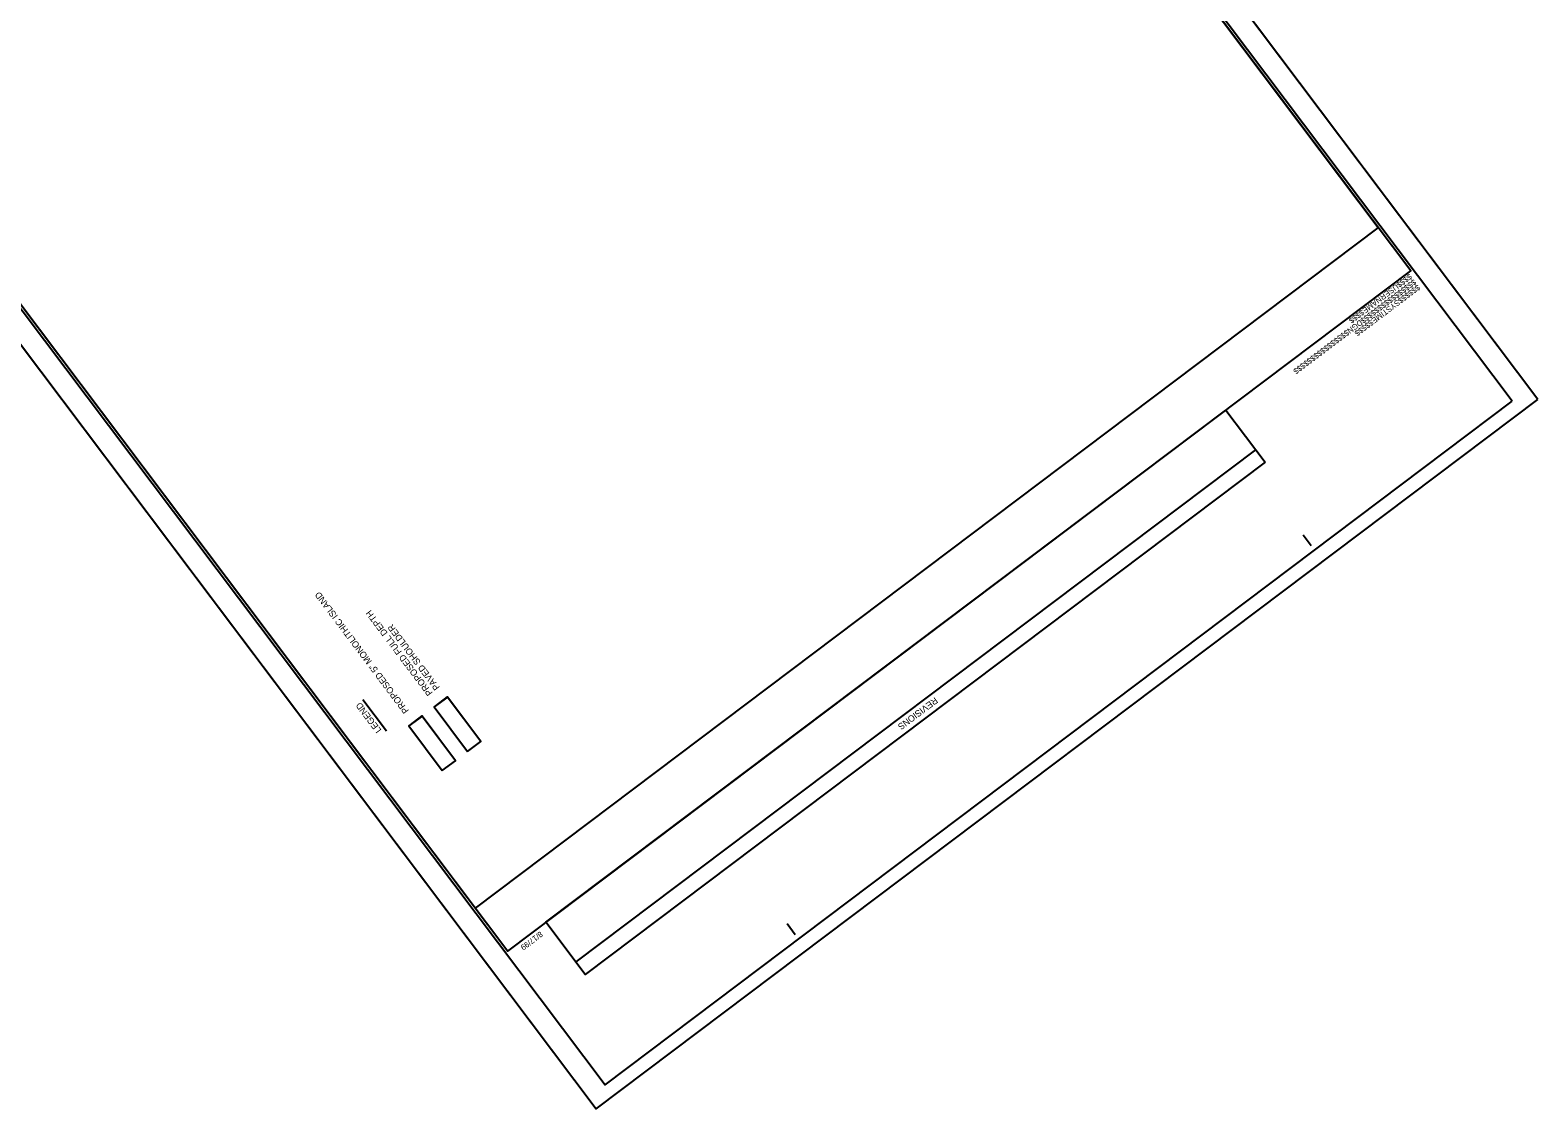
# Model space of a CAD drawing. Extents: x 1262749 to 1264921, y 774795 to 776798.
# Drawn here: x 1263520 to 1264921, y 774795 to 775796 of the extents above; entities that cross this region are included whole.
import ezdxf

# ---------------------------------------------------------------- set-up
doc = ezdxf.new("R2010")
doc.units = 0
for name, color, linetype in [('Old_Level_1', 7, 'Continuous'), ('Prop Shade Light', 7, 'Continuous'), ('Prop Shade Medium', 7, 'Continuous'), ('Sheet Block Revision CELL', 7, 'Continuous'), ('Sheet Clip Boundary CELL', 7, 'Continuous'), ('Sheet Cutting Line CELL', 7, 'Continuous'), ('Sheet Layout Plan Border', 7, 'Continuous'), ('Sheet Plan CELL', 7, 'Continuous'), ('Sheet Plan Layout CELL', 7, 'Continuous'), ('Sheet Plot Border Inside CELL', 7, 'Continuous'), ('Sheet Plot Border Outside CELL', 7, 'Continuous')]:
    doc.layers.add(name, color=color, linetype=linetype)

msp = doc.modelspace()

# ---------------------------------------------------------------- linework, layer by layer
at = {"layer": 'Prop Shade Light'}
msp.add_lwpolyline([(1263926.7, 775126.5), (1263939, 775135.7), (1263907.9, 775177.1), (1263895.7, 775167.9)], close=True, dxfattribs=at)
at = {"layer": 'Prop Shade Medium'}
msp.add_lwpolyline([(1263903.1, 775108.8), (1263915.4, 775117.9), (1263884.3, 775159.4), (1263872, 775150.2)], close=True, dxfattribs=at)
at = {"layer": 'Sheet Block Revision CELL'}
msp.add_line((1264658.6, 775406.8), (1264027.1, 774931.1), dxfattribs=at)
msp.add_lwpolyline([(1264667.4, 775395.2), (1264035.8, 774919.5), (1263999.4, 774967.9), (1264630.9, 775443.5)], close=True, dxfattribs=at)
at = {"layer": 'Sheet Clip Boundary CELL'}
msp.add_lwpolyline([(1264772.6, 775612.8), (1264136.1, 776457.8), (1263888.7, 776271.4), (1263888.7, 776271.4), (1263542, 776010.3), (1263546.7, 776013.8), (1263492.1, 776075), (1263297.4, 775826.1), (1263933.9, 774981.1)], close=True, dxfattribs=at)
at = {"layer": 'Sheet Cutting Line CELL'}
for p, q in [((1264920.8, 775453.5), (1263907.9, 776798.2)), ((1263033.3, 776139.4), (1264046.2, 774794.7)), ((1264046.2, 774794.7), (1264920.8, 775453.5))]:
    msp.add_line(p, q, dxfattribs=at)
at = {"layer": 'Sheet Layout Plan Border'}
msp.add_lwpolyline([(1264772.6, 775612.8), (1263930.3, 776731.1), (1263260.5, 776226.6), (1263374.4, 776075.5), (1263205.4, 775948.2), (1263933.9, 774981.1)], close=True, dxfattribs=at)
at = {"layer": 'Sheet Plan CELL'}
for p, q in [((1264802.7, 775572.9), (1264802.7, 775572.9)), ((1264710.3, 775317.4), (1264702.8, 775327.4)), ((1263851.2, 775145.4), (1263829.4, 775174.4)), ((1264231, 774956.4), (1264223.5, 774966.4)), ((1263964, 774941.2), (1263964, 774941.2))]:
    msp.add_line(p, q, dxfattribs=at)
for points in [[(1263061.5, 776139.4), (1263964, 774941.2), (1264802.7, 775572.9), (1263900.2, 776771.1)], [(1263926.7, 775126.5), (1263939, 775135.7), (1263907.8, 775177.2), (1263895.6, 775168)], [(1263903.1, 775108.8), (1263915.4, 775117.9), (1263884.2, 775159.5), (1263872, 775150.3)]]:
    msp.add_lwpolyline(points, close=True, dxfattribs=at)
at = {"layer": 'Sheet Plan Layout CELL'}
msp.add_lwpolyline([(1263964, 774941.2), (1264802.7, 775572.9), (1263900.2, 776771), (1263230.4, 776266.6), (1263374.4, 776075.5), (1263205.4, 775948.2)], close=True, dxfattribs=at)
at = {"layer": 'Sheet Plot Border Inside CELL'}
msp.add_lwpolyline([(1264897, 775451.8), (1263894.7, 776782.5), (1263052, 776147.8), (1264054.3, 774817.1)], close=True, dxfattribs=at)
at = {"layer": 'Sheet Plot Border Outside CELL'}
msp.add_lwpolyline([(1264920.8, 775453.5), (1263907.9, 776798.2), (1263033.3, 776139.4), (1264046.2, 774794.7)], close=True, dxfattribs=at)

# ---------------------------------------------------------------- texts
at = {"layer": 'Old_Level_1'}
for s, p in [('PROPOSED 5" MONOLITHIC ISLAND', (1263872.4, 775164.5)), ('PROPOSED FULL DEPTH', (1263894.5, 775181)), ('PAVED SHOULDER', (1263901.1, 775186.1)), ('LEGEND', (1263846.9, 775146.4))]:
    msp.add_text(s, height=6, rotation=126.8862, dxfattribs=at).set_placement(p)
at = {"layer": 'Sheet Block Revision CELL'}
msp.add_text('REVISIONS', height=6, rotation=216.9874, dxfattribs=at).set_placement((1264360.6, 775177.3))
at = {"layer": 'Sheet Plan CELL'}
for s, p in [('$$$$USERNAME$$$$', (1264801.4, 775570.6)), ('$$$$$$$$$$$$$$$$DGN$$$$$$$$$$$$$$$$', (1264805.4, 775565.4)), ('$$$$$$SYSTIME$$$$$', (1264809, 775560.5)), ('8/17/99', (1263994, 774959.8))]:
    msp.add_text(s, height=5.25, rotation=216.9874, dxfattribs=at).set_placement(p)

doc.saveas('drawing.dxf')
